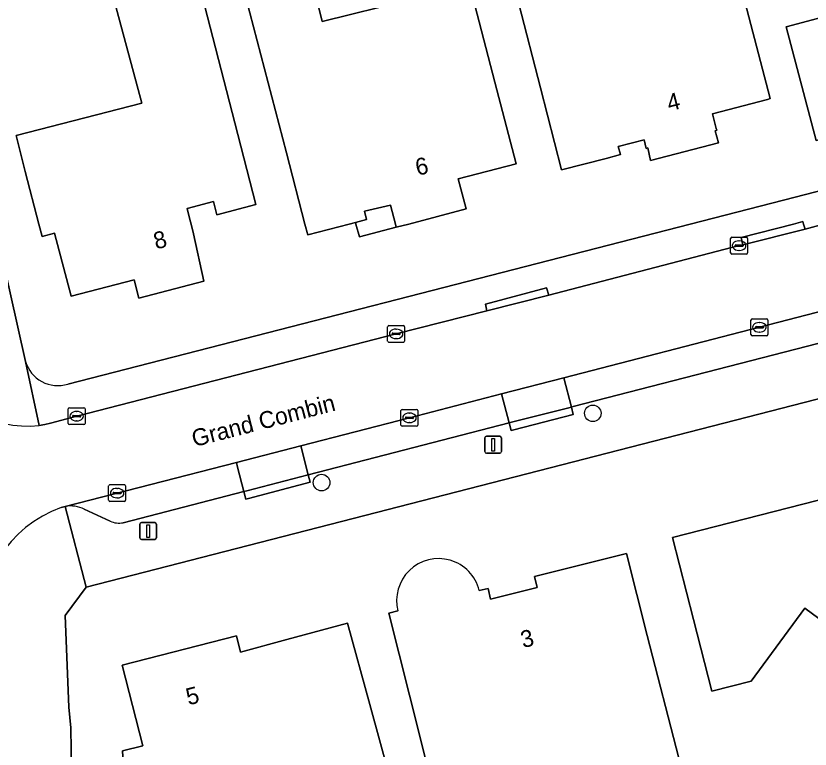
# Model space of a CAD drawing. Extents: x 158835 to 160077, y 386387 to 387778.
# Drawn here: x 159520.69 to 159567.65, y 386718.95 to 386762.31 of the extents above; entities that cross this region are included whole.
import ezdxf

# ---------------------------------------------------------------- set-up
doc = ezdxf.new("R2010")
doc.units = 0
for name, color, linetype in [('IMGEO_Boom', 7, 'Continuous'), ('IMGEO_Erf', 7, 'Continuous'), ('IMGEO_Kolk', 7, 'Continuous'), ('IMGEO_Lichtmast', 7, 'Continuous'), ('IMGEO_Openbare_ruimte_label', 7, 'Continuous'), ('IMGEO_Pand', 7, 'Continuous'), ('IMGEO_Pand_nummerreeks', 7, 'Continuous'), ('IMGEO_Parkeervlak_open', 7, 'Continuous'), ('IMGEO_Rijbaan_lokaal_open', 7, 'Continuous'), ('IMGEO_Voetpad_open', 7, 'Continuous')]:
    doc.layers.add(name, color=color, linetype=linetype)

msp = doc.modelspace()

# ---------------------------------------------------------------- linework, layer by layer
at = {"layer": 'IMGEO_Boom'}
for centre in [(159554.798, 386738.808), (159538.767, 386734.711)]:
    msp.add_circle(centre, 0.489, dxfattribs=at)
at = {"layer": 'IMGEO_Erf'}
for points in [[(159571.89, 386781.884), (159572.057, 386781.565), (159573.424, 386776.409), (159574.602, 386776.722), (159581.341, 386763.781), (159581.252, 386763.729), (159578.387, 386762.942), (159579.584, 386758.372), (159583.625, 386759.428), (159583.762, 386759.137), (159574.185, 386756.588), (159568.01, 386754.944), (159566.222, 386761.661), (159571.402, 386763.039), (159571.888, 386761.254), (159572.856, 386761.512), (159570.024, 386772.006), (159569.113, 386771.763), (159566.784, 386780.517)], [(159546.503, 386768.043), (159549.015, 386758.395), (159550.275, 386753.556), (159546.846, 386752.663), (159547.311, 386750.893), (159543.914, 386750), (159543.184, 386749.808), (159541.002, 386749.238), (159540.795, 386750), (159540.77, 386750.099), (159540.39, 386750), (159537.949, 386749.364), (159537.783, 386750), (159536.688, 386754.203), (159534.093, 386764.16), (159537.15, 386764.919), (159538.203, 386764.406), (159538.808, 386761.97), (159543.905, 386763.236), (159543.126, 386766.371), (159543.688, 386767.344)], [(159543.184, 386749.808), (159543.133, 386750), (159542.837, 386751.121), (159541.293, 386750.752), (159541.419, 386750.268), (159540.77, 386750.099), (159540.795, 386750), (159541.002, 386749.238)], [(159546.149, 386705.02), (159540.327, 386703.374), (159537.752, 386712.48), (159532.281, 386712.169), (159527.289, 386711.885), (159527.025, 386716.527), (159527.131, 386716.528), (159526.993, 386718.851), (159528.19, 386719.148), (159526.968, 386723.917), (159533.73, 386725.646), (159533.978, 386724.677), (159536.711, 386725.424), (159540.305, 386726.406), (159541.623, 386721.583)]]:
    msp.add_lwpolyline(points, close=True, dxfattribs=at)
for points in [[(159529.272, 386772.972), (159533.64, 386755.991), (159534.886, 386751.149), (159532.566, 386750.552), (159532.528, 386750.698), (159532.367, 386751.324), (159530.817, 386750.925), (159530.984, 386750.274), (159531.055, 386750), (159531.203, 386749.425), (159531.809, 386746.626), (159527.958, 386745.616), (159527.686, 386746.709), (159523.96, 386745.742), (159522.985, 386749.464), (159522.244, 386749.269), (159522.055, 386750), (159521.252, 386753.113), (159520.707, 386755.224), (159528.134, 386757.141), (159525.572, 386766.689)], [(159561.493, 386771.955), (159564.028, 386762.251), (159565.292, 386757.413), (159565.129, 386757.37), (159561.884, 386756.52), (159562.098, 386755.646), (159562.138, 386755.54), (159562.039, 386755.512), (159562.22, 386754.796), (159558.213, 386753.765), (159558.044, 386754.499), (159557.948, 386754.469), (159557.829, 386754.974), (159556.303, 386754.586), (159556.428, 386754.101), (159555.581, 386753.883), (159552.949, 386753.207), (159551.705, 386758.05), (159549.148, 386768.007)], [(159516.181, 386761.62), (159519.013, 386752.552), (159518.811, 386752.518), (159519.43, 386750), (159521.264, 386741.879)], [(159523.764, 386740.534), (159560.559, 386750), (159566.77, 386751.594), (159585.367, 386756.394)], [(159595.413, 386746.689), (159524.846, 386728.532), (159523.607, 386726.844), (159523.829, 386721.437), (159523.936, 386720.207), (159523.989, 386717.606)], [(159576.147, 386720.781), (159567.339, 386727.287), (159564.162, 386722.97), (159561.837, 386722.373), (159560.747, 386726.615), (159559.503, 386731.458), (159572.371, 386734.763)], [(159548.085, 386728.335), (159548.605, 386728.457), (159548.757, 386727.815), (159551.512, 386728.516), (159551.353, 386729.157), (159556.798, 386730.526), (159558.017, 386725.677), (159563.63, 386703.915)], [(159554.124, 386718.288), (159545.468, 386716.177), (159543.969, 386722.142), (159542.75, 386726.991), (159543.279, 386727.128)]]:
    msp.add_lwpolyline(points, dxfattribs=at)
for centre, radius, start, end in [((159523.172, 386742.43), 1.986, 196.1068, 287.3327), ((159545.681, 386727.736), 2.478, 13.9887, 194.2072)]:
    msp.add_arc(centre, radius, start, end, dxfattribs=at)
at = {"layer": 'IMGEO_Kolk'}
for p, q in [((159562.947, 386748.296), (159562.947, 386749.148)), ((159563.022, 386749.222), (159563.874, 386749.222)), ((159563.435, 386749.002), (159563.46, 386749.002)), ((159563.948, 386749.148), (159563.948, 386748.296)), ((159563.206, 386748.716), (159563.206, 386748.728)), ((159563.644, 386748.679), (159563.246, 386748.679)), ((159563.249, 386748.765), (159563.647, 386748.765)), ((159563.458, 386748.442), (159563.433, 386748.442)), ((159563.69, 386748.728), (159563.69, 386748.716)), ((159563.874, 386748.222), (159563.022, 386748.222)), ((159564.148, 386743.467), (159564.148, 386744.319)), ((159564.223, 386744.393), (159565.075, 386744.393)), ((159564.636, 386744.173), (159564.661, 386744.173)), ((159565.149, 386744.319), (159565.149, 386743.467)), ((159542.672, 386743.077), (159542.672, 386743.929)), ((159542.747, 386744.003), (159543.599, 386744.003)), ((159543.16, 386743.783), (159543.185, 386743.783)), ((159543.673, 386743.929), (159543.673, 386743.077)), ((159564.407, 386743.887), (159564.407, 386743.899)), ((159564.845, 386743.85), (159564.447, 386743.85)), ((159564.45, 386743.936), (159564.848, 386743.936)), ((159564.891, 386743.899), (159564.891, 386743.887)), ((159542.931, 386743.497), (159542.931, 386743.509)), ((159543.369, 386743.46), (159542.971, 386743.46)), ((159542.974, 386743.546), (159543.372, 386743.546)), ((159543.183, 386743.223), (159543.158, 386743.223)), ((159543.415, 386743.509), (159543.415, 386743.497)), ((159565.075, 386743.393), (159564.223, 386743.393)), ((159564.659, 386743.613), (159564.634, 386743.613)), ((159543.599, 386743.003), (159542.747, 386743.003)), ((159523.788, 386738.214), (159523.788, 386739.066)), ((159523.863, 386739.14), (159524.715, 386739.14)), ((159524.789, 386739.066), (159524.789, 386738.214)), ((159543.534, 386739.041), (159544.386, 386739.041)), ((159524.047, 386738.634), (159524.047, 386738.646)), ((159524.485, 386738.597), (159524.087, 386738.597)), ((159524.09, 386738.683), (159524.488, 386738.683)), ((159524.276, 386738.92), (159524.301, 386738.92)), ((159524.531, 386738.646), (159524.531, 386738.634)), ((159543.459, 386738.115), (159543.459, 386738.967)), ((159543.718, 386738.535), (159543.718, 386738.547)), ((159543.761, 386738.584), (159544.159, 386738.584)), ((159543.947, 386738.821), (159543.972, 386738.821)), ((159544.202, 386738.547), (159544.202, 386738.535)), ((159544.46, 386738.967), (159544.46, 386738.115)), ((159524.715, 386738.14), (159523.863, 386738.14)), ((159524.299, 386738.36), (159524.274, 386738.36)), ((159544.156, 386738.498), (159543.758, 386738.498)), ((159543.97, 386738.261), (159543.945, 386738.261)), ((159544.386, 386738.041), (159543.534, 386738.041)), ((159526.179, 386733.664), (159526.179, 386734.516)), ((159526.254, 386734.59), (159527.106, 386734.59)), ((159526.667, 386734.37), (159526.692, 386734.37)), ((159527.18, 386734.516), (159527.18, 386733.664)), ((159526.438, 386734.084), (159526.438, 386734.096)), ((159526.876, 386734.047), (159526.478, 386734.047)), ((159526.481, 386734.133), (159526.879, 386734.133)), ((159526.922, 386734.096), (159526.922, 386734.084)), ((159527.106, 386733.59), (159526.254, 386733.59)), ((159526.69, 386733.81), (159526.665, 386733.81))]:
    msp.add_line(p, q, dxfattribs=at)
for points in [[(159562.947, 386748.296), (159562.947, 386749.148)], [(159563.022, 386749.222), (159563.874, 386749.222)], [(159563.948, 386749.148), (159563.948, 386748.296)], [(159563.874, 386748.222), (159563.022, 386748.222)], [(159564.148, 386743.467), (159564.148, 386744.319)], [(159564.223, 386744.393), (159565.075, 386744.393)], [(159565.149, 386744.319), (159565.149, 386743.467)], [(159542.672, 386743.077), (159542.672, 386743.929)], [(159542.747, 386744.003), (159543.599, 386744.003)], [(159543.673, 386743.929), (159543.673, 386743.077)], [(159565.075, 386743.393), (159564.223, 386743.393)], [(159543.599, 386743.003), (159542.747, 386743.003)], [(159523.788, 386738.214), (159523.788, 386739.066)], [(159523.863, 386739.14), (159524.715, 386739.14)], [(159524.789, 386739.066), (159524.789, 386738.214)], [(159543.534, 386739.041), (159544.386, 386739.041)], [(159543.459, 386738.115), (159543.459, 386738.967)], [(159544.46, 386738.967), (159544.46, 386738.115)], [(159524.715, 386738.14), (159523.863, 386738.14)], [(159544.386, 386738.041), (159543.534, 386738.041)], [(159526.179, 386733.664), (159526.179, 386734.516)], [(159526.254, 386734.59), (159527.106, 386734.59)], [(159527.18, 386734.516), (159527.18, 386733.664)], [(159527.106, 386733.59), (159526.254, 386733.59)]]:
    msp.add_lwpolyline(points, dxfattribs=at)
for centre, radius, start, end in [((159563.024, 386749.146), 0.0765, 91.552, 178.448), ((159563.024, 386749.146), 0.0765, 91.552, 178.448), ((159563.872, 386749.146), 0.0765, 1.552, 88.448), ((159563.872, 386749.146), 0.0765, 1.552, 88.448), ((159563.246, 386748.725), 0.0403, 85.8775, 175.7526), ((159563.243, 386748.715), 0.0366, 178.938, 274.7102), ((159563.647, 386748.722), 0.043, 264.8664, 352.4533), ((159563.651, 386748.727), 0.0386, 1.7309, 96.639), ((159563.024, 386748.298), 0.0765, 181.552, 268.448), ((159563.024, 386748.298), 0.0765, 181.552, 268.448), ((159563.872, 386748.298), 0.0765, 271.552, 358.448), ((159563.872, 386748.298), 0.0765, 271.552, 358.448), ((159564.225, 386744.317), 0.0765, 91.552, 178.448), ((159564.225, 386744.317), 0.0765, 91.552, 178.448), ((159565.073, 386744.317), 0.0765, 1.552, 88.448), ((159565.073, 386744.317), 0.0765, 1.552, 88.448), ((159542.749, 386743.927), 0.0765, 91.552, 178.448), ((159542.749, 386743.927), 0.0765, 91.552, 178.448), ((159543.597, 386743.927), 0.0765, 1.552, 88.448), ((159543.597, 386743.927), 0.0765, 1.552, 88.448), ((159564.447, 386743.896), 0.0403, 85.8775, 175.7526), ((159564.444, 386743.886), 0.0366, 178.938, 274.7102), ((159564.848, 386743.893), 0.043, 264.8664, 352.4533), ((159564.852, 386743.898), 0.0386, 1.7309, 96.639), ((159542.971, 386743.506), 0.0403, 85.8775, 175.7526), ((159542.968, 386743.496), 0.0366, 178.938, 274.7102), ((159543.372, 386743.503), 0.043, 264.8664, 352.4533), ((159543.376, 386743.508), 0.0386, 1.7309, 96.639), ((159564.225, 386743.469), 0.0765, 181.552, 268.448), ((159564.225, 386743.469), 0.0765, 181.552, 268.448), ((159565.073, 386743.469), 0.0765, 271.552, 358.448), ((159565.073, 386743.469), 0.0765, 271.552, 358.448), ((159542.749, 386743.079), 0.0765, 181.552, 268.448), ((159542.749, 386743.079), 0.0765, 181.552, 268.448), ((159543.597, 386743.079), 0.0765, 271.552, 358.448), ((159543.597, 386743.079), 0.0765, 271.552, 358.448), ((159523.865, 386739.064), 0.0765, 91.552, 178.448), ((159523.865, 386739.064), 0.0765, 91.552, 178.448), ((159524.713, 386739.064), 0.0765, 1.552, 88.448), ((159524.713, 386739.064), 0.0765, 1.552, 88.448), ((159543.536, 386738.965), 0.0765, 91.552, 178.448), ((159543.536, 386738.965), 0.0765, 91.552, 178.448), ((159544.384, 386738.965), 0.0765, 1.552, 88.448), ((159544.384, 386738.965), 0.0765, 1.552, 88.448), ((159524.087, 386738.643), 0.0403, 85.8775, 175.7526), ((159524.084, 386738.633), 0.0366, 178.938, 274.7102), ((159524.488, 386738.64), 0.043, 264.8664, 352.4533), ((159524.492, 386738.645), 0.0386, 1.7309, 96.639), ((159543.758, 386738.544), 0.0403, 85.8775, 175.7526), ((159543.755, 386738.534), 0.0366, 178.938, 274.7102), ((159544.159, 386738.541), 0.043, 264.8664, 352.4533), ((159544.163, 386738.546), 0.0386, 1.7309, 96.639), ((159523.865, 386738.216), 0.0765, 181.552, 268.448), ((159523.865, 386738.216), 0.0765, 181.552, 268.448), ((159524.713, 386738.216), 0.0765, 271.552, 358.448), ((159524.713, 386738.216), 0.0765, 271.552, 358.448), ((159543.536, 386738.117), 0.0765, 181.552, 268.448), ((159543.536, 386738.117), 0.0765, 181.552, 268.448), ((159544.384, 386738.117), 0.0765, 271.552, 358.448), ((159544.384, 386738.117), 0.0765, 271.552, 358.448), ((159526.256, 386734.514), 0.0765, 91.552, 178.448), ((159526.256, 386734.514), 0.0765, 91.552, 178.448), ((159527.104, 386734.514), 0.0765, 1.552, 88.448), ((159527.104, 386734.514), 0.0765, 1.552, 88.448), ((159526.478, 386734.093), 0.0403, 85.8775, 175.7526), ((159526.475, 386734.083), 0.0366, 178.938, 274.7102), ((159526.879, 386734.09), 0.043, 264.8664, 352.4533), ((159526.883, 386734.095), 0.0386, 1.7309, 96.639), ((159526.256, 386733.666), 0.0765, 181.552, 268.448), ((159526.256, 386733.666), 0.0765, 181.552, 268.448), ((159527.104, 386733.666), 0.0765, 271.552, 358.448), ((159527.104, 386733.666), 0.0765, 271.552, 358.448)]:
    msp.add_arc(centre, radius, start, end, dxfattribs=at)
for centre, major_axis, ratio, start_param, end_param in [((159563.434, 386748.722), (-0.387, 0.002), 0.722429, 4.712389, 7.853982), ((159563.459, 386748.722), (-0.39, 0.002), 0.717154, 1.570796, 4.712389), ((159564.635, 386743.893), (-0.387, 0.002), 0.722429, 4.712389, 7.853982), ((159564.66, 386743.893), (-0.39, 0.002), 0.717154, 1.570796, 4.712389), ((159543.159, 386743.503), (-0.387, 0.002), 0.722429, 4.712389, 7.853982), ((159543.184, 386743.503), (-0.39, 0.002), 0.717154, 1.570796, 4.712389), ((159524.275, 386738.64), (-0.387, 0.002), 0.722429, 4.712389, 7.853982), ((159524.3, 386738.64), (-0.39, 0.002), 0.717154, 1.570796, 4.712389), ((159543.946, 386738.541), (-0.387, 0.002), 0.722429, 4.712389, 7.853982), ((159543.971, 386738.541), (-0.39, 0.002), 0.717154, 1.570796, 4.712389), ((159526.666, 386734.09), (-0.387, 0.002), 0.722429, 4.712389, 7.853982), ((159526.691, 386734.09), (-0.39, 0.002), 0.717154, 1.570796, 4.712389)]:
    msp.add_ellipse(centre, major_axis=major_axis, ratio=ratio, start_param=start_param, end_param=end_param, dxfattribs=at)
at = {"layer": 'IMGEO_Lichtmast'}
for p, q in [((159548.41, 386736.551), (159548.41, 386737.351)), ((159548.41, 386737.351), (159548.41, 386736.551)), ((159548.51, 386737.451), (159549.3, 386737.451)), ((159549.3, 386737.451), (159548.51, 386737.451)), ((159549.4, 386737.351), (159549.4, 386736.551)), ((159549.4, 386736.551), (159549.4, 386737.351)), ((159549.3, 386736.451), (159548.51, 386736.451)), ((159548.51, 386736.451), (159549.3, 386736.451)), ((159528.016, 386731.447), (159528.016, 386732.247)), ((159528.016, 386732.247), (159528.016, 386731.447)), ((159528.116, 386732.347), (159528.906, 386732.347)), ((159528.906, 386732.347), (159528.116, 386732.347)), ((159529.006, 386732.247), (159529.006, 386731.447)), ((159529.006, 386731.447), (159529.006, 386732.247)), ((159528.906, 386731.347), (159528.116, 386731.347)), ((159528.116, 386731.347), (159528.906, 386731.347))]:
    msp.add_line(p, q, dxfattribs=at)
for points in [[(159548.83, 386737.326), (159548.98, 386737.326), (159548.98, 386736.576), (159548.83, 386736.576), (159548.83, 386737.326)], [(159528.436, 386732.222), (159528.586, 386732.222), (159528.586, 386731.472), (159528.436, 386731.472), (159528.436, 386732.222)]]:
    msp.add_lwpolyline(points, dxfattribs=at)
for centre, start, end in [((159548.51, 386737.351), 90, 180), ((159548.51, 386737.351), 90, 180), ((159549.3, 386737.351), 0, 90), ((159549.3, 386737.351), 360, 90), ((159548.51, 386736.551), 180, 270), ((159548.51, 386736.551), 180, 270), ((159549.3, 386736.551), 270, 0), ((159549.3, 386736.551), 270, 0), ((159528.116, 386732.247), 90, 180), ((159528.116, 386732.247), 90, 180), ((159528.906, 386732.247), 0, 90), ((159528.906, 386732.247), 360, 90), ((159528.116, 386731.447), 180, 270), ((159528.116, 386731.447), 180, 270), ((159528.906, 386731.447), 270, 0), ((159528.906, 386731.447), 270, 0)]:
    msp.add_arc(centre, 0.1, start, end, dxfattribs=at)
at = {"layer": 'IMGEO_Pand'}
for points in [[(159571.89, 386781.884), (159566.784, 386780.517), (159569.113, 386771.763), (159570.024, 386772.006), (159572.856, 386761.512), (159571.888, 386761.254), (159571.402, 386763.039), (159566.222, 386761.661), (159568.01, 386754.944), (159574.185, 386756.588), (159583.762, 386759.137), (159583.625, 386759.428), (159579.584, 386758.372), (159578.387, 386762.942), (159581.252, 386763.729), (159581.341, 386763.781), (159574.602, 386776.722), (159573.424, 386776.409), (159572.057, 386781.565)], [(159543.914, 386750), (159547.311, 386750.893), (159546.846, 386752.663), (159550.275, 386753.556), (159549.015, 386758.395), (159546.503, 386768.043), (159543.688, 386767.344), (159543.126, 386766.371), (159543.905, 386763.236), (159538.808, 386761.97), (159538.203, 386764.406), (159537.15, 386764.919), (159534.093, 386764.16), (159536.688, 386754.203), (159537.783, 386750), (159537.949, 386749.364), (159540.39, 386750), (159540.77, 386750.099), (159541.419, 386750.268), (159541.293, 386750.752), (159542.837, 386751.121), (159543.133, 386750), (159543.184, 386749.808)], [(159591.302, 386741.165), (159591.04, 386741.346), (159590.15, 386740.147), (159585.606, 386734.045), (159579.612, 386732.51), (159577.952, 386733.737), (159577.343, 386736.048), (159575.271, 386735.51), (159574.091, 386735.206), (159574.246, 386734.606), (159572.525, 386734.163), (159572.371, 386734.763), (159559.503, 386731.458), (159560.747, 386726.615), (159561.837, 386722.373), (159564.162, 386722.97), (159567.339, 386727.287), (159576.147, 386720.781)], [(159526.968, 386723.917), (159528.19, 386719.148), (159526.993, 386718.851), (159527.131, 386716.528), (159527.025, 386716.527), (159527.289, 386711.885), (159532.281, 386712.169), (159537.752, 386712.48), (159540.327, 386703.374), (159546.149, 386705.02), (159541.623, 386721.583), (159540.305, 386726.406), (159536.711, 386725.424), (159533.978, 386724.677), (159533.73, 386725.646)]]:
    msp.add_lwpolyline(points, close=True, dxfattribs=at)
for points in [[(159525.572, 386766.689), (159528.134, 386757.141), (159520.707, 386755.224), (159521.252, 386753.113), (159522.055, 386750), (159522.244, 386749.269), (159522.985, 386749.464), (159523.96, 386745.742), (159527.686, 386746.709), (159527.958, 386745.616), (159531.809, 386746.626), (159531.203, 386749.425), (159531.055, 386750), (159530.984, 386750.274), (159530.817, 386750.925), (159532.367, 386751.324), (159532.528, 386750.698), (159532.566, 386750.552), (159534.886, 386751.149), (159533.64, 386755.991), (159529.272, 386772.972)], [(159549.148, 386768.007), (159551.705, 386758.05), (159552.949, 386753.207), (159555.581, 386753.883), (159556.428, 386754.101), (159556.303, 386754.586), (159557.829, 386754.974), (159557.948, 386754.469), (159558.044, 386754.499), (159558.213, 386753.765), (159562.22, 386754.796), (159562.039, 386755.512), (159562.138, 386755.54), (159562.098, 386755.646), (159561.884, 386756.52), (159565.129, 386757.37), (159565.292, 386757.413), (159564.028, 386762.251), (159561.493, 386771.955)], [(159543.279, 386727.128), (159542.75, 386726.991), (159543.969, 386722.142), (159545.468, 386716.177), (159554.124, 386718.288), (159557.463, 386705.724), (159555.329, 386702.95), (159556.98, 386697.244), (159558.058, 386696.441), (159563.63, 386703.915), (159558.017, 386725.677), (159556.798, 386730.526), (159551.353, 386729.157), (159551.512, 386728.516), (159548.757, 386727.815), (159548.605, 386728.457), (159548.085, 386728.335)]]:
    msp.add_lwpolyline(points, dxfattribs=at)
msp.add_arc((159545.681, 386727.736), 2.478, 13.9887, 194.2072, dxfattribs=at)
at = {"layer": 'IMGEO_Parkeervlak_open'}
for points in [[(159587.161, 386747.852), (159586.721, 386749.604), (159583.604, 386748.805), (159564.648, 386743.894), (159553.095, 386740.906), (159553.535, 386739.175), (159553.636, 386739.201)], [(159553.095, 386740.906), (159549.411, 386739.953), (159549.851, 386738.239), (159550.001, 386738.278), (159553.535, 386739.175)], [(159549.851, 386738.239), (159549.411, 386739.953), (159543.96, 386738.543), (159537.537, 386736.888), (159537.981, 386735.166)], [(159537.537, 386736.888), (159533.73, 386735.908), (159533.804, 386735.62), (159534.175, 386734.185), (159534.344, 386734.229), (159537.981, 386735.166)]]:
    msp.add_lwpolyline(points, close=True, dxfattribs=at)
for points in [[(159533.804, 386735.62), (159533.73, 386735.908), (159523.605, 386733.299)], [(159527.031, 386732.337), (159534.175, 386734.185), (159533.804, 386735.62)], [(159524.74, 386733.132), (159526.272, 386732.431)]]:
    msp.add_lwpolyline(points, dxfattribs=at)
for centre, radius, start, end in [((159523.932, 386731.578), 1.751, 62.5124, 100.7471), ((159526.794, 386733.534), 1.22, 244.679, 281.201)]:
    msp.add_arc(centre, radius, start, end, dxfattribs=at)
at = {"layer": 'IMGEO_Rijbaan_lokaal_open'}
for points in [[(159564.648, 386743.894), (159583.604, 386748.805), (159586.721, 386749.604), (159586.622, 386750), (159585.522, 386754.384), (159581.126, 386753.285), (159568.43, 386750), (159567.345, 386749.705), (159563.672, 386748.773), (159563.448, 386748.721), (159552.191, 386745.792), (159548.543, 386744.875), (159543.172, 386743.502), (159524.29, 386738.639), (159522.743, 386738.227), (159522.405, 386738.15), (159522.062, 386738.094)], [(159523.378, 386733.241), (159523.605, 386733.299), (159533.73, 386735.908), (159537.537, 386736.888), (159543.96, 386738.543), (159549.411, 386739.953), (159553.095, 386740.906), (159564.648, 386743.894)]]:
    msp.add_lwpolyline(points, dxfattribs=at)
for centre, radius, start, end in [((159521.362, 386743.502), 5.453, 192.4656, 277.3782), ((159525.907, 386726.323), 7.366, 110.0787, 184.8196)]:
    msp.add_arc(centre, radius, start, end, dxfattribs=at)
at = {"layer": 'IMGEO_Voetpad_open'}
for points in [[(159522.062, 386738.094), (159521.264, 386741.879), (159519.43, 386750), (159518.811, 386752.518), (159519.013, 386752.552), (159516.181, 386761.62)], [(159523.605, 386733.299), (159524.846, 386728.532), (159595.413, 386746.689), (159599.84, 386747.828), (159603.124, 386748.673), (159608.282, 386750), (159626.26, 386754.636), (159627.547, 386754.968), (159630.619, 386759.07)], [(159630.619, 386759.07), (159629.306, 386758.731), (159606.552, 386752.858), (159595.477, 386750), (159594.987, 386749.874), (159593.176, 386749.406), (159589.539, 386748.466), (159589.456, 386748.445), (159587.161, 386747.852), (159553.636, 386739.201), (159553.535, 386739.175), (159553.646, 386738.739), (159550.126, 386737.827), (159549.968, 386737.786), (159549.851, 386738.239), (159537.981, 386735.166), (159538.09, 386734.738), (159534.447, 386733.777), (159534.292, 386733.736), (159534.175, 386734.185), (159527.031, 386732.337)], [(159585.367, 386756.394), (159566.77, 386751.594), (159560.559, 386750), (159523.764, 386740.534)], [(159521.264, 386741.879), (159522.062, 386738.094), (159522.405, 386738.15), (159522.743, 386738.227), (159524.29, 386738.639), (159543.172, 386743.502), (159548.543, 386744.875), (159548.455, 386745.269), (159552.066, 386746.23), (159552.191, 386745.792), (159563.448, 386748.721), (159563.672, 386748.773), (159563.568, 386749.205), (159566.658, 386750), (159567.21, 386750.142), (159567.254, 386750), (159567.345, 386749.705), (159568.43, 386750), (159581.126, 386753.285), (159585.522, 386754.384), (159587.756, 386755.079)], [(159452.919, 386610.024), (159466.865, 386626.712), (159480.297, 386643.692), (159492.025, 386659.896), (159492.426, 386660.371), (159500, 386671.529), (159500.252, 386671.907), (159506.854, 386682.053), (159520.825, 386705.101), (159521.901, 386707.468), (159522.762, 386709.923), (159523.4, 386712.444), (159523.81, 386715.012), (159523.989, 386717.606), (159523.936, 386720.207), (159523.829, 386721.437), (159523.607, 386726.844), (159524.846, 386728.532), (159523.605, 386733.299), (159523.378, 386733.241)], [(159526.272, 386732.431), (159524.74, 386733.132)]]:
    msp.add_lwpolyline(points, dxfattribs=at)
for points in [[(159567.345, 386749.705), (159567.254, 386750), (159567.21, 386750.142), (159566.658, 386750), (159563.568, 386749.205), (159563.672, 386748.773)], [(159548.543, 386744.875), (159552.191, 386745.792), (159552.066, 386746.23), (159548.455, 386745.269)], [(159553.646, 386738.739), (159553.535, 386739.175), (159550.001, 386738.278), (159549.851, 386738.239), (159549.968, 386737.786), (159550.126, 386737.827)], [(159538.09, 386734.738), (159537.981, 386735.166), (159534.344, 386734.229), (159534.175, 386734.185), (159534.292, 386733.736), (159534.447, 386733.777)]]:
    msp.add_lwpolyline(points, close=True, dxfattribs=at)
for centre, radius, start, end in [((159521.362, 386743.502), 5.453, 192.4656, 277.3782), ((159523.172, 386742.43), 1.986, 196.1068, 287.3327), ((159525.907, 386726.323), 7.366, 110.0787, 184.8196), ((159523.932, 386731.578), 1.751, 62.5124, 100.7471), ((159526.794, 386733.534), 1.22, 244.679, 281.201)]:
    msp.add_arc(centre, radius, start, end, dxfattribs=at)

# ---------------------------------------------------------------- texts
at = {"layer": 'IMGEO_Openbare_ruimte_label'}
msp.add_text('Grand Combin', height=1, rotation=14.481, dxfattribs=at).set_placement((159531.237, 386736.808))
at = {"layer": 'IMGEO_Pand_nummerreeks'}
for s, rotation, p in [('4', 14.4292, (159559.322, 386756.652)), ('6', 12.0655, (159544.426, 386752.853)), ('8', 14.696, (159528.982, 386748.49)), ('3', 14.2758, (159550.677, 386724.919)), ('5', 14.3429, (159530.894, 386721.535))]:
    msp.add_text(s, height=1, rotation=rotation, dxfattribs=at).set_placement(p)

doc.saveas('drawing.dxf')
